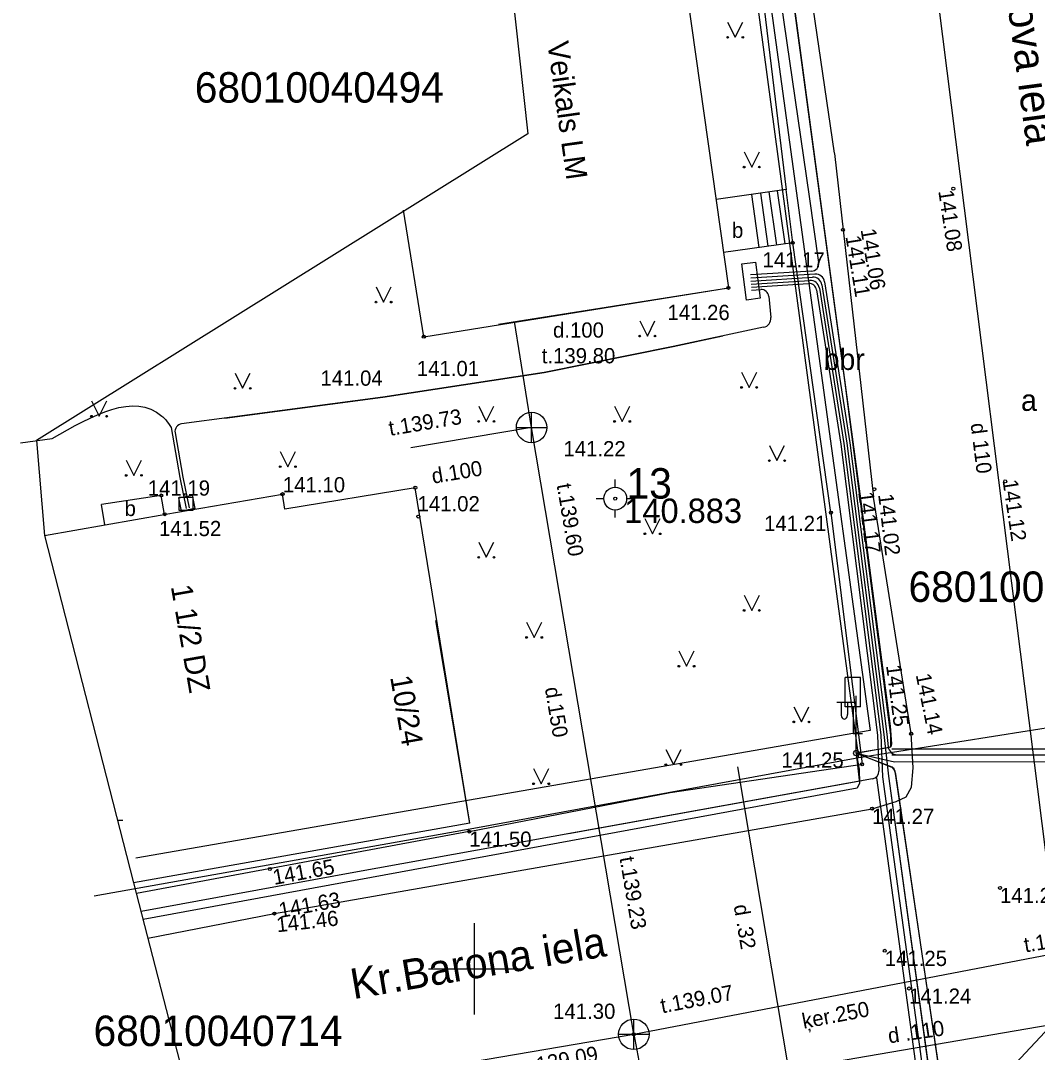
# Model space of a CAD drawing. Extents: x 728710 to 728960, y 272811 to 273475.
# Drawn here: x 728785.11 to 728818.5, y 273097.26 to 273131.14 of the extents above; entities that cross this region are included whole.
import ezdxf

# ---------------------------------------------------------------- set-up
doc = ezdxf.new("R2010")
doc.units = 0
for name, color, linetype in [('GEOD_ELEM_####_TKST_#', 7, 'Continuous'), ('Level 10', 7, 'Continuous'), ('Level 15', 7, 'Continuous'), ('Level 17', 7, 'Continuous'), ('Level 23', 7, 'Continuous'), ('Level 26', 7, 'Continuous'), ('Level 29', 7, 'Continuous'), ('Level 3', 7, 'Continuous'), ('Level 36', 7, 'Continuous'), ('Level 4', 7, 'Continuous'), ('Level 48', 7, 'Continuous'), ('Level 49', 7, 'Continuous'), ('Level 50', 7, 'Continuous'), ('Level 54', 7, 'Continuous'), ('Level 55', 7, 'Continuous'), ('Level 56', 7, 'Continuous'), ('Level 57', 7, 'Continuous'), ('Level 58', 7, 'Continuous'), ('Level 59', 7, 'Continuous'), ('Level 60', 7, 'Continuous'), ('Level 62', 7, 'Continuous'), ('Level 63', 7, 'Continuous'), ('Level 9', 7, 'Continuous'), ('RAMI_UZMR_####_####_#', 7, 'Continuous'), ('RELJ_ELEM_####_####_#', 7, 'Continuous'), ('ROBZ_ELEM_####_####_#', 7, 'Continuous'), ('ROBZ_KADS_####_TKST_#', 7, 'Continuous'), ('ROBZ_UZMR_####_####_#', 7, 'Continuous'), ('TERT_ELEM_####_####_#', 7, 'Continuous'), ('TERT_KONT_####_####_#', 7, 'Continuous')]:
    doc.layers.add(name, color=color, linetype=linetype)

msp = doc.modelspace()

# ---------------------------------------------------------------- linework, layer by layer
at = {"layer": 'GEOD_ELEM_####_TKST_#'}
for points in [[(728812.551, 273107.084), (728813.681, 273107.292), (728813.683, 273107.676), (728812.175, 273119.32), (728807.481, 273154.061), (728806.142, 273164.357), (728806.065, 273164.722), (728806.247, 273164.866), (728807.003, 273165.091)], [(728812.551, 273107.084), (728813.808, 273106.798), (728827.684, 273106.812), (728831.005, 273108.951), (728843.77, 273111.313)], [(728812.551, 273107.084), (728812.657, 273106.097), (728812.582, 273105.93), (728789.128, 273101.623)], [(728821.778, 273054.372), (728821.536, 273054.45), (728821.45, 273054.614), (728821.201, 273057.003), (728816.435, 273088.774), (728813.852, 273106.392), (728813.783, 273106.59), (728812.551, 273107.084)]]:
    msp.add_lwpolyline(points, dxfattribs=at)
at = {"layer": 'Level 10'}
for p, q in [((728804.633, 273115.818), (728804.633, 273116.068)), ((728804.008, 273115.443), (728804.258, 273115.443)), ((728805.008, 273115.443), (728805.258, 273115.443)), ((728804.633, 273114.818), (728804.633, 273115.068)), ((728800, 273101.5), (728800, 273100)), ((728798.5, 273100), (728800, 273100)), ((728800, 273100), (728800, 273098.5)), ((728800, 273100), (728801.5, 273100))]:
    msp.add_line(p, q, dxfattribs=at)
for radius in [0.375, 0.05]:
    msp.add_circle((728804.633, 273115.443), radius, dxfattribs=at)
at = {"layer": 'Level 15'}
for points in [[(728809.235, 273123.213), (728809.395, 273122.023), (728808.949, 273121.963), (728808.789, 273123.153)], [(728790.828, 273115.119), (728790.389, 273115.032), (728790.303, 273115.464), (728790.742, 273115.551)], [(728790.763, 273115.048), (728790.316, 273115.048), (728790.316, 273115.488), (728790.763, 273115.488)]]:
    msp.add_lwpolyline(points, close=True, dxfattribs=at)
at = {"layer": 'Level 17'}
for p, q in [((728810.333, 273096.686), (728808.658, 273106.631)), ((728845.326, 273102.67), (728810.333, 273096.686))]:
    msp.add_line(p, q, dxfattribs=at)
msp.add_lwpolyline([(728814.387, 273138.519), (728819.492, 273098.009)], dxfattribs=at)
at = {"layer": 'Level 23'}
for points in [[(728801.886, 273117.777), (728801.325, 273121.255)], [(728805.243, 273097.85), (728801.886, 273117.777), (728797.924, 273117.11)], [(728805.243, 273097.85), (728821.624, 273100.995), (728813.478, 273092.29)], [(728790.731, 273095.382), (728805.243, 273097.85), (728806.524, 273091.029)]]:
    msp.add_lwpolyline(points, dxfattribs=at)
at = {"layer": 'Level 26'}
for p, q in [((728812.551, 273107.084), (728812.551, 273108.967)), ((728812.551, 273108.751), (728811.916, 273108.746)), ((728812.051, 273108.747), (728812.051, 273108.355)), ((728812.261, 273108.749), (728812.261, 273108.355))]:
    msp.add_line(p, q, dxfattribs=at)
msp.add_circle((728812.551, 273107.084), 0.09, dxfattribs=at)
msp.add_ellipse((728812.156, 273108.355), major_axis=(0, 0.151), ratio=0.695971, start_param=1.570796, end_param=4.712389, dxfattribs=at)
at = {"layer": 'Level 29'}
for p, q in [((728801.886, 273117.277), (728801.886, 273118.277)), ((728801.386, 273117.777), (728802.386, 273117.777)), ((728805.243, 273097.35), (728805.243, 273098.35)), ((728804.743, 273097.85), (728805.743, 273097.85))]:
    msp.add_line(p, q, dxfattribs=at)
for centre in [(728801.886, 273117.777), (728805.243, 273097.85)]:
    msp.add_circle(centre, 0.5, dxfattribs=at)
at = {"layer": 'Level 3'}
for p, q in [((728806.814, 273133.293), (728808.351, 273122.364)), ((728798.348, 273120.759), (728797.682, 273124.91)), ((728798.348, 273120.759), (728808.351, 273122.364)), ((728800.795, 273121.176), (728808.351, 273122.364)), ((728789.873, 273114.932), (728793.701, 273115.587)), ((728793.781, 273115.101), (728793.701, 273115.587)), ((728798.067, 273115.8), (728793.781, 273115.101)), ((728799.863, 273104.782), (728798.067, 273115.8)), ((728785.888, 273114.234), (728789.873, 273114.932)), ((728799.863, 273104.782), (728798.74, 273111.436)), ((728799.863, 273104.782), (728788.818, 273102.829))]:
    msp.add_line(p, q, dxfattribs=at)
at = {"layer": 'Level 36'}
for p, q in [((728813.714, 273107.229), (728827.671, 273107.231)), ((728813.714, 273107.029), (728827.671, 273107.031)), ((728813.216, 273106.275), (728814.871, 273094.169)), ((728813.612, 273106.329), (728815.267, 273094.223))]:
    msp.add_line(p, q, dxfattribs=at)
for points in [[(728791.813, 273118.086), (728797.004, 273118.778), (728802.303, 273119.588), (728806.535, 273120.438), (728808.165, 273120.783)], [(728812.731, 273106.174), (728803.101, 273104.435)], [(728813.414, 273106.302), (728815.05, 273094.332)]]:
    msp.add_lwpolyline(points, dxfattribs=at)
at = {"layer": 'Level 4'}
for p, q in [((728807.002, 273152.348), (728810.246, 273125.587)), ((728811.715, 273114.983), (728810.469, 273123.845)), ((728814.353, 273107.731), (728813.116, 273115.489)), ((728811.715, 273114.983), (728812.742, 273106.717)), ((728806.433, 273105.789), (728812.742, 273106.717)), ((728799.84, 273104.509), (728806.433, 273105.789))]:
    msp.add_line(p, q, dxfattribs=at)
for points in [[(728811.836, 273126.782), (728808.082, 273152.433), (728807.534, 273154.175), (728806.989, 273154.338)], [(728811.835, 273126.775), (728813.116, 273115.489), (728813.116, 273115.489)], [(728789.286, 273101.006), (728793.44, 273101.816), (728813.067, 273105.258), (728813.855, 273105.497), (728814.183, 273105.647), (728814.358, 273105.969), (728814.419, 273106.601), (728814.353, 273107.731)], [(728799.84, 273104.509), (728788.911, 273102.469)]]:
    msp.add_lwpolyline(points, dxfattribs=at)
at = {"layer": 'Level 48'}
for centre in [(728815.736, 273125.619), (728812.11, 273124.271), (728810.465, 273123.845), (728808.351, 273122.364), (728808.351, 273122.364), (728798.348, 273120.759), (728798.348, 273120.759), (728817.442, 273116.008), (728789.724, 273115.546), (728789.724, 273115.546), (728793.701, 273115.587), (728793.71, 273115.591), (728798.067, 273115.8), (728798.067, 273115.8), (728813.143, 273115.752), (728789.84, 273114.929), (728798.166, 273114.853), (728811.715, 273114.983), (728814.353, 273107.722), (728812.742, 273106.717), (728813.067, 273105.258), (728799.84, 273104.509), (728793.293, 273103.281), (728817.27, 273102.659), (728793.44, 273101.816), (728813.485, 273100.593), (728814.283, 273099.354), (728805.243, 273097.85)]:
    msp.add_circle(centre, 0.05, dxfattribs=at)
at = {"layer": 'Level 49'}
for p, q in [((728812.689, 273109.573), (728812.189, 273109.573)), ((728812.189, 273108.604), (728812.189, 273109.573)), ((728812.689, 273108.604), (728812.689, 273109.573)), ((728812.689, 273108.604), (728812.189, 273108.604)), ((728812.443, 273108.604), (728812.443, 273107.726)), ((728812.443, 273107.726), (728812.758, 273107.726))]:
    msp.add_line(p, q, dxfattribs=at)
at = {"layer": 'Level 9'}
for p, q in [((728810.248, 273125.594), (728807.944, 273125.27)), ((728809.361, 273123.69), (728809.115, 273125.435)), ((728809.66, 273123.732), (728809.414, 273125.477)), ((728809.937, 273123.771), (728809.692, 273125.516)), ((728810.211, 273123.809), (728809.966, 273125.554)), ((728810.469, 273123.845), (728810.248, 273125.594)), ((728810.469, 273123.845), (728808.19, 273123.525)), ((728789.724, 273115.546), (728787.759, 273115.246)), ((728789.83, 273114.925), (728789.724, 273115.546)), ((728787.875, 273114.582), (728787.759, 273115.246))]:
    msp.add_line(p, q, dxfattribs=at)
msp.add_lwpolyline([(728788.291, 273104.881), (728788.465, 273104.881)], dxfattribs=at)
at = {"layer": 'RAMI_UZMR_####_####_#'}
msp.add_lwpolyline([(728788.892, 273161.497), (728790.999, 273149.932), (728793.805, 273144.064), (728799.858, 273144.727), (728801.765, 273127.417), (728785.623, 273117.349), (728785.888, 273114.234), (728788.818, 273102.829), (728792.114, 273090.001), (728794.527, 273084.256), (728808.426, 273087.287), (728810.894, 273070.336), (728816.634, 273032.011)], dxfattribs=at)
at = {"layer": 'RELJ_ELEM_####_####_#'}
for points in [[(728807.003, 273165.091), (728806.309, 273164.885), (728806.073, 273164.759), (728806.082, 273164.765), (728806.142, 273164.357), (728807.497, 273153.999), (728812.666, 273115.604), (728813.66, 273107.967), (728813.707, 273107.385), (728813.681, 273107.292), (728813.602, 273107.257), (728812.551, 273107.084)], [(728812.551, 273107.084), (728813.18, 273106.941), (728813.808, 273106.798), (728827.684, 273106.812), (728831.005, 273108.951), (728843.77, 273111.313)], [(728812.551, 273107.084), (728812.644, 273106.556), (728812.657, 273106.097), (728812.582, 273105.93), (728789.128, 273101.623)], [(728812.551, 273107.084), (728813.167, 273106.837), (728813.712, 273106.629), (728813.818, 273106.491), (728816.417, 273088.868), (728821.181, 273057.115), (728821.45, 273054.614), (728821.507, 273054.486), (728821.778, 273054.372)]]:
    msp.add_lwpolyline(points, dxfattribs=at)
at = {"layer": 'ROBZ_ELEM_####_####_#'}
for points in [[(728807.526, 273147.836), (728813.011, 273107.831)], [(728813.011, 273107.831), (728788.891, 273103.639)]]:
    msp.add_lwpolyline(points, dxfattribs=at)
at = {"layer": 'ROBZ_UZMR_####_####_#'}
for p, q in [((728812.63, 273106.926), (728809.109, 273133.219)), ((728824.732, 273108.848), (728812.63, 273106.926)), ((728812.63, 273106.926), (728799.992, 273104.613)), ((728799.992, 273104.613), (728787.517, 273102.391))]:
    msp.add_line(p, q, dxfattribs=at)
at = {"layer": 'TERT_ELEM_####_####_#'}
for p, q in [((728811.081, 273122.912), (728809.08, 273122.788)), ((728809.086, 273122.688), (728811.193, 273122.819)), ((728809.098, 273122.488), (728811.024, 273122.608)), ((728809.104, 273122.388), (728810.985, 273122.505)), ((728809.111, 273122.289), (728809.412, 273122.307)), ((728785.106, 273117.275), (728786.139, 273117.422)), ((728813.896, 273107.029), (728827.6, 273107.031))]:
    msp.add_line(p, q, dxfattribs=at)
for points in [[(728807.157, 273153.303), (728807.729, 273148.716), (728808.834, 273140.506), (728809.798, 273133.659), (728810.998, 273125.369), (728811.313, 273123.197)], [(728809.092, 273122.588), (728811.109, 273122.713)], [(728811.339, 273122.355), (728812.143, 273117.249), (728813.351, 273107.683), (728813.414, 273106.302)], [(728811.423, 273122.46), (728812.242, 273117.263), (728813.45, 273107.695), (728813.612, 273106.329)], [(728811.508, 273122.566), (728812.341, 273117.277), (728813.549, 273107.707), (728813.598, 273107.294)], [(728809.677, 273122.081), (728809.743, 273121.389)], [(728811.247, 273122.294), (728812.044, 273117.235), (728813.251, 273107.671), (728813.291, 273106.493)], [(728809.506, 273121.068), (728806.535, 273120.438), (728802.303, 273119.588), (728797.004, 273118.778), (728790.392, 273117.897)], [(728790.049, 273117.773), (728790.333, 273116.131), (728790.539, 273115.12)], [(728790.179, 273117.606), (728790.431, 273116.149), (728790.637, 273115.14)], [(728813.085, 273106.238), (728796.045, 273103.161), (728789.061, 273101.885)], [(728813.414, 273106.302), (728815.05, 273094.332)], [(728813.612, 273106.329), (728815.267, 273094.223)]]:
    msp.add_lwpolyline(points, dxfattribs=at)
for centre, radius, start, end in [((728811.066, 273123.161), 0.25, 273.5498, 8.2577), ((728811.127, 273122.414), 0.3, 8.95, 93.5498), ((728811.212, 273122.519), 0.3, 8.95, 93.5498), ((728811, 273122.256), 0.25, 8.95, 93.5498), ((728811.042, 273122.308), 0.3, 8.95, 93.5498), ((728809.428, 273122.058), 0.25, 5.4443, 93.5498), ((728809.444, 273121.361), 0.3, 281.9628, 5.4443), ((728790.425, 273117.649), 0.25, 97.5932, 189.8128), ((728813.896, 273107.329), 0.3, 186.7703, 270.0082), ((728813.041, 273106.484), 0.25, 280.2364, 1.911)]:
    msp.add_arc(centre, radius, start, end, dxfattribs=at)
msp.add_spline([(728786.139, 273117.422), (728789.747, 273118.154), (728789.873, 273118.029), (728790.049, 273117.773)], degree=3, dxfattribs=at)
at = {"layer": 'TERT_KONT_####_####_#'}
for p, q in [((728808.324, 273131.092), (728808.574, 273130.592)), ((728808.574, 273130.592), (728808.824, 273131.092)), ((728808.867, 273126.83), (728809.117, 273126.33)), ((728809.117, 273126.33), (728809.367, 273126.83)), ((728796.778, 273122.396), (728797.028, 273121.896)), ((728797.028, 273121.896), (728797.278, 273122.396)), ((728805.438, 273121.281), (728805.688, 273120.781)), ((728805.688, 273120.781), (728805.938, 273121.281)), ((728792.148, 273119.565), (728792.398, 273119.065)), ((728792.398, 273119.065), (728792.648, 273119.565)), ((728808.782, 273119.593), (728809.032, 273119.093)), ((728809.032, 273119.093), (728809.282, 273119.593)), ((728787.432, 273118.649), (728787.682, 273118.149)), ((728787.682, 273118.149), (728787.932, 273118.649)), ((728800.15, 273118.478), (728800.4, 273117.978)), ((728800.4, 273117.978), (728800.65, 273118.478)), ((728804.612, 273118.478), (728804.862, 273117.978)), ((728804.862, 273117.978), (728805.112, 273118.478)), ((728793.634, 273116.99), (728793.884, 273116.49)), ((728793.884, 273116.49), (728794.134, 273116.99)), ((728809.696, 273117.19), (728809.946, 273116.69)), ((728809.946, 273116.69), (728810.196, 273117.19)), ((728788.575, 273116.704), (728788.825, 273116.204)), ((728788.825, 273116.204), (728789.075, 273116.704)), ((728805.609, 273114.788), (728805.859, 273114.288)), ((728805.859, 273114.288), (728806.109, 273114.788)), ((728800.15, 273114.015), (728800.4, 273113.515)), ((728800.4, 273113.515), (728800.65, 273114.015)), ((728808.867, 273112.27), (728809.117, 273111.77)), ((728809.117, 273111.77), (728809.367, 273112.27)), ((728801.722, 273111.384), (728801.972, 273110.884)), ((728801.972, 273110.884), (728802.222, 273111.384)), ((728806.724, 273110.44), (728806.974, 273109.94)), ((728806.974, 273109.94), (728807.224, 273110.44)), ((728810.497, 273108.609), (728810.747, 273108.109)), ((728810.747, 273108.109), (728810.997, 273108.609)), ((728806.295, 273107.208), (728806.545, 273106.708)), ((728806.545, 273106.708), (728806.795, 273107.208)), ((728801.951, 273106.578), (728802.201, 273106.078)), ((728802.201, 273106.078), (728802.451, 273106.578))]:
    msp.add_line(p, q, dxfattribs=at)
for centre, radius in [((728808.324, 273130.592), 0.028), ((728808.824, 273130.592), 0.0263), ((728808.867, 273126.33), 0.028), ((728809.367, 273126.33), 0.0263), ((728796.777, 273121.896), 0.028), ((728797.277, 273121.896), 0.0263), ((728805.437, 273120.78), 0.028), ((728805.937, 273120.78), 0.0263), ((728792.147, 273119.064), 0.028), ((728792.647, 273119.064), 0.0263), ((728808.781, 273119.093), 0.028), ((728809.281, 273119.093), 0.0263), ((728787.431, 273118.149), 0.028), ((728787.931, 273118.149), 0.0263), ((728800.15, 273117.977), 0.028), ((728800.65, 273117.977), 0.0263), ((728804.612, 273117.977), 0.028), ((728805.112, 273117.977), 0.0263), ((728809.696, 273116.69), 0.028), ((728810.196, 273116.69), 0.0263), ((728788.575, 273116.204), 0.028), ((728789.075, 273116.204), 0.0263), ((728793.633, 273116.49), 0.028), ((728794.133, 273116.49), 0.0263), ((728805.609, 273114.287), 0.028), ((728806.109, 273114.287), 0.0263), ((728800.15, 273113.515), 0.028), ((728800.65, 273113.515), 0.0263), ((728808.867, 273111.77), 0.028), ((728809.367, 273111.77), 0.0263), ((728801.722, 273110.883), 0.028), ((728802.222, 273110.883), 0.0263), ((728806.724, 273109.939), 0.028), ((728807.224, 273109.939), 0.0263), ((728810.496, 273108.109), 0.028), ((728810.996, 273108.109), 0.0263), ((728806.295, 273106.707), 0.028), ((728806.795, 273106.707), 0.0263), ((728801.951, 273106.078), 0.028), ((728802.451, 273106.078), 0.0263)]:
    msp.add_circle(centre, radius, dxfattribs=at)

# ---------------------------------------------------------------- texts
at = {"layer": 'Level 29'}
msp.add_text('141.30', height=0.5, dxfattribs=at).set_placement((728802.593, 273098.357))
at = {"layer": 'Level 50'}
for p in [(728808.468, 273124.006), (728788.52, 273114.87)]:
    msp.add_text('b', height=0.5, dxfattribs=at).set_placement(p)
at = {"layer": 'Level 54'}
for s, rotation, p in [('A.Rekašova iela', 277.641, (728816.855, 273136.586)), ('Kr.Barona iela', 9.638, (728796.031, 273099.001))]:
    msp.add_text(s, height=1, rotation=rotation, dxfattribs=at).set_placement(p)
at = {"layer": 'Level 55'}
for s, rotation, p in [('d 110', 277.1825, (728816.302, 273117.898)), ('d .32', 279.5604, (728808.521, 273102.076)), ('d .110', 8.2194, (728813.628, 273097.552))]:
    msp.add_text(s, height=0.5, rotation=rotation, dxfattribs=at).set_placement(p)
at = {"layer": 'Level 56'}
msp.add_text(' 141.22', height=0.5, dxfattribs=at).set_placement((728802.747, 273116.832))
at = {"layer": 'Level 57'}
for s, rotation, p in [('141.08', 278.573, (728815.242, 273125.544)), ('141.11', 279.2762, (728812.194, 273124.05)), ('141.06', 279.5392, (728812.69, 273124.275)), ('141.12', 278.4301, (728817.352, 273116.034)), ('141.17', 277.1192, (728812.612, 273115.645)), ('141.02', 276.7044, (728813.267, 273115.578)), ('141.25', 277.3584, (728813.527, 273109.959)), ('141.14', 281.5231, (728814.499, 273109.654)), ('141.65', 10.3842, (728793.435, 273102.756)), ('141.63', 10.3842, (728793.631, 273101.672)), ('141.46', 6.3923, (728793.532, 273101.199))]:
    msp.add_text(s, height=0.5, rotation=rotation, dxfattribs=at).set_placement(p)
for s, p in [(' 141.17', (728809.285, 273123.034)), (' 141.26', (728806.163, 273121.307)), (' 141.01', (728797.931, 273119.465)), (' 141.04', (728794.766, 273119.15)), (' 141.19', (728789.096, 273115.54)), (' 141.10', (728793.532, 273115.649)), (' 141.02', (728797.955, 273115.025)), (' 141.21', (728809.337, 273114.379)), (' 141.52', (728789.464, 273114.21)), ('141.25', (728810.092, 273106.605)), ('141.27', (728813.067, 273104.758)), ('141.50', (728799.84, 273104.009)), ('141.23', (728817.27, 273102.159)), ('141.25', (728813.485, 273100.093)), ('141.24', (728814.283, 273098.854))]:
    msp.add_text(s, height=0.5, dxfattribs=at).set_placement(p)
at = {"layer": 'Level 58'}
for s, p in [('bbr', (728811.476, 273119.667)), ('a', (728817.959, 273118.324))]:
    msp.add_text(s, height=0.7, dxfattribs=at).set_placement(p)
at = {"layer": 'Level 59'}
for s, rotation, p in [('Veikals LM', 278.014, (728802.399, 273130.41)), ('1 1/2 DZ', 279.946, (728790.036, 273112.558))]:
    msp.add_text(s, height=0.7, rotation=rotation, dxfattribs=at).set_placement(p)
at = {"layer": 'Level 60'}
for s, p in [('d.100', (728802.59, 273120.729)), ('t.139.80', (728802.22, 273119.885))]:
    msp.add_text(s, height=0.5, dxfattribs=at).set_placement(p)
for s, rotation, p in [('t.139.73', 9.563, (728797.24, 273117.501)), ('d.100', 9.563, (728798.649, 273115.931)), ('t.139.60', 279.563, (728802.709, 273115.896)), ('d.150', 279.563, (728802.32, 273109.217)), ('t.139.23', 279.563, (728804.773, 273103.645)), ('t.138.78', 9.383, (728818.101, 273100.536)), ('t.139.07', 10.868, (728806.173, 273098.537)), ('ķer.250', 10.868, (728810.821, 273098.031)), ('t.139.09', 10.868, (728801.729, 273096.526))]:
    msp.add_text(s, height=0.5, rotation=rotation, dxfattribs=at).set_placement(p)
at = {"layer": 'Level 62'}
msp.add_text('10/24', height=0.7, rotation=279.946, dxfattribs=at).set_placement((728797.239, 273109.582))
at = {"layer": 'Level 63'}
for s, height, p in [(' 13', 1, (728804.633, 273115.443)), (' 140.883', 0.8, (728804.633, 273114.643))]:
    msp.add_text(s, height=height, dxfattribs=at).set_placement(p)
at = {"layer": 'ROBZ_KADS_####_TKST_#'}
for s, p in [('68010040494', (728790.825, 273128.447)), ('68010040723', (728814.264, 273112.05)), ('68010040714', (728787.501, 273097.465))]:
    msp.add_text(s, height=1, dxfattribs=at).set_placement(p)

doc.saveas('drawing.dxf')
